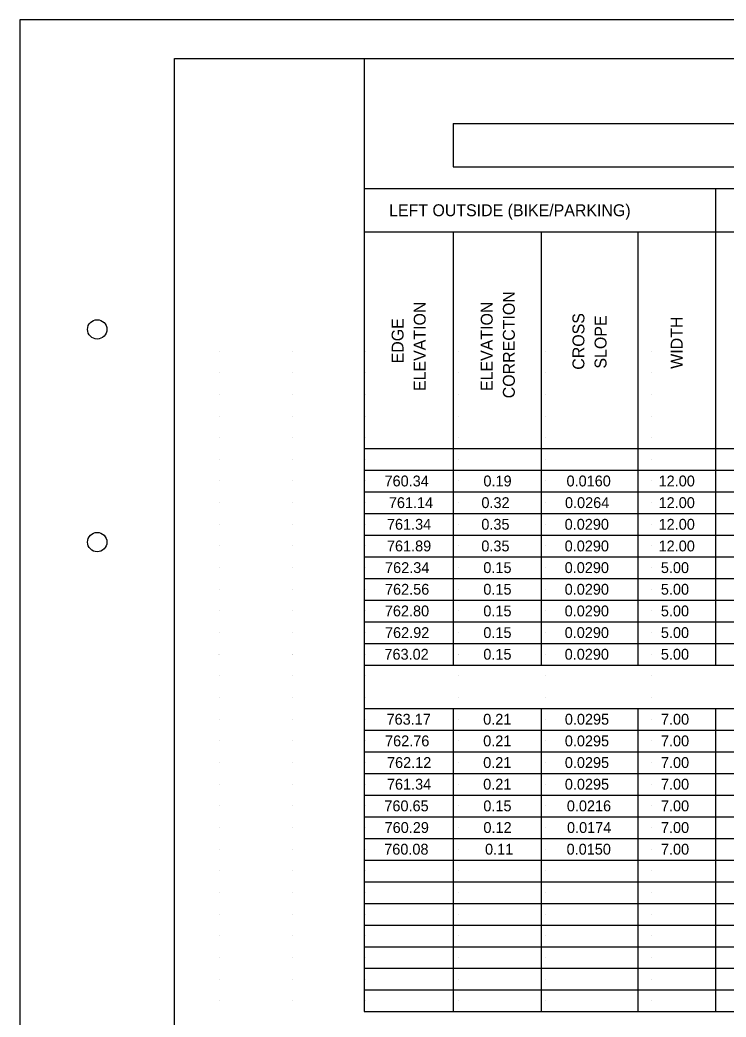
# Model space of a CAD drawing. Extents: x -15.4 to 18.6, y -12.6 to 9.4.
# Drawn here: x -15.36 to -6.22, y -3.5 to 9.39 of the extents above; entities that cross this region are included whole.
import ezdxf

# ---------------------------------------------------------------- set-up
doc = ezdxf.new("R2010")
doc.units = 0
for name, color, linetype in [('SH_Border', 7, 'Continuous'), ('SH_Cut_Line', 7, 'Continuous'), ('SH_Data', 7, 'Continuous'), ('SH_Text', 7, 'Continuous')]:
    doc.layers.add(name, color=color, linetype=linetype)

msp = doc.modelspace()

# ---------------------------------------------------------------- linework, layer by layer
at = {"layer": 'SH_Border'}
msp.add_lwpolyline([(-13.357, 8.888), (18.143, 8.888), (18.143, -12.112), (-13.357, -12.112)], close=True, dxfattribs=at)
for centre in [(-14.357, 5.388), (-14.357, 2.638)]:
    msp.add_circle(centre, 0.125, dxfattribs=at)
at = {"layer": 'SH_Cut_Line'}
msp.add_lwpolyline([(-15.357, -12.612), (18.643, -12.612), (18.643, 9.388), (-15.357, 9.388)], close=True, dxfattribs=at)
at = {"layer": 'SH_Data'}
for p, q in [((-10.905, 8.888), (13.093, 8.888)), ((-10.905, 8.888), (-10.905, -3.432)), ((-9.752, 8.048), (11.215, 8.048)), ((-9.752, 8.048), (-9.752, 7.488)), ((-9.752, 7.488), (11.215, 7.488)), ((-10.905, 7.208), (13.093, 7.208)), ((-6.359, 7.208), (-6.359, 1.048)), ((-10.905, 6.648), (11.791, 6.648)), ((-9.752, 6.648), (-9.752, 1.048)), ((-8.616, 6.648), (-8.616, 1.048)), ((-7.364, 6.648), (-7.364, 1.048)), ((-12.782, 5.108), (-12.782, 5.108)), ((-11.832, 5.108), (-11.832, 5.108)), ((-10.882, 5.108), (-10.882, 5.108)), ((-9.682, 5.108), (-9.682, 5.108)), ((-8.557, 5.108), (-8.557, 5.108)), ((-7.182, 5.108), (-7.182, 5.108)), ((-12.782, 4.828), (-12.782, 4.828)), ((-11.832, 4.828), (-11.832, 4.828)), ((-10.882, 4.828), (-10.882, 4.828)), ((-9.682, 4.828), (-9.682, 4.828)), ((-8.557, 4.828), (-8.557, 4.828)), ((-7.182, 4.828), (-7.182, 4.828)), ((-12.782, 4.548), (-12.782, 4.548)), ((-11.832, 4.548), (-11.832, 4.548)), ((-10.882, 4.548), (-10.882, 4.548)), ((-9.682, 4.548), (-9.682, 4.548)), ((-8.557, 4.548), (-8.557, 4.548)), ((-7.182, 4.548), (-7.182, 4.548)), ((-12.782, 4.268), (-12.782, 4.268)), ((-11.832, 4.268), (-11.832, 4.268)), ((-10.882, 4.268), (-10.882, 4.268)), ((-9.682, 4.268), (-9.682, 4.268)), ((-8.557, 4.268), (-8.557, 4.268)), ((-7.182, 4.268), (-7.182, 4.268)), ((-12.782, 3.988), (-12.782, 3.988)), ((-11.832, 3.988), (-11.832, 3.988)), ((-10.882, 3.988), (-10.882, 3.988)), ((-9.682, 3.988), (-9.682, 3.988)), ((-8.557, 3.988), (-8.557, 3.988)), ((-7.182, 3.988), (-7.182, 3.988)), ((-10.905, 3.848), (13.093, 3.848)), ((-12.782, 3.708), (-12.782, 3.708)), ((-11.832, 3.708), (-11.832, 3.708)), ((-10.882, 3.708), (-10.882, 3.708)), ((-9.682, 3.708), (-9.682, 3.708)), ((-8.557, 3.708), (-8.557, 3.708)), ((-7.182, 3.708), (-7.182, 3.708)), ((-10.905, 3.568), (13.093, 3.568)), ((-12.782, 3.428), (-12.782, 3.428)), ((-11.832, 3.428), (-11.832, 3.428)), ((-10.882, 3.428), (-10.882, 3.428)), ((-9.682, 3.428), (-9.682, 3.428)), ((-8.557, 3.428), (-8.557, 3.428)), ((-7.182, 3.428), (-7.182, 3.428)), ((-10.905, 3.288), (13.093, 3.288)), ((-12.782, 3.148), (-12.782, 3.148)), ((-11.832, 3.148), (-11.832, 3.148)), ((-10.882, 3.148), (-10.882, 3.148)), ((-9.682, 3.148), (-9.682, 3.148)), ((-8.557, 3.148), (-8.557, 3.148)), ((-7.182, 3.148), (-7.182, 3.148)), ((-10.905, 3.008), (13.093, 3.008)), ((-12.782, 2.868), (-12.782, 2.868)), ((-11.832, 2.868), (-11.832, 2.868)), ((-10.882, 2.868), (-10.882, 2.868)), ((-9.682, 2.868), (-9.682, 2.868)), ((-8.557, 2.868), (-8.557, 2.868)), ((-7.182, 2.868), (-7.182, 2.868)), ((-10.905, 2.728), (13.093, 2.728)), ((-12.782, 2.588), (-12.782, 2.588)), ((-11.832, 2.588), (-11.832, 2.588)), ((-10.882, 2.588), (-10.882, 2.588)), ((-9.682, 2.588), (-9.682, 2.588)), ((-8.557, 2.588), (-8.557, 2.588)), ((-7.182, 2.588), (-7.182, 2.588)), ((-10.905, 2.448), (13.093, 2.448)), ((-12.782, 2.308), (-12.782, 2.308)), ((-11.832, 2.308), (-11.832, 2.308)), ((-10.882, 2.308), (-10.882, 2.308)), ((-9.682, 2.308), (-9.682, 2.308)), ((-8.557, 2.308), (-8.557, 2.308)), ((-7.182, 2.308), (-7.182, 2.308)), ((-10.905, 2.168), (13.093, 2.168)), ((-12.782, 2.028), (-12.782, 2.028)), ((-11.832, 2.028), (-11.832, 2.028)), ((-10.882, 2.028), (-10.882, 2.028)), ((-9.682, 2.028), (-9.682, 2.028)), ((-8.557, 2.028), (-8.557, 2.028)), ((-7.182, 2.028), (-7.182, 2.028)), ((-10.905, 1.888), (13.093, 1.888)), ((-12.782, 1.748), (-12.782, 1.748)), ((-12.782, 1.748), (-12.782, 1.748)), ((-11.832, 1.748), (-11.832, 1.748)), ((-11.832, 1.748), (-11.832, 1.748)), ((-10.882, 1.748), (-10.882, 1.748)), ((-10.882, 1.748), (-10.882, 1.748)), ((-9.682, 1.748), (-9.682, 1.748)), ((-9.682, 1.748), (-9.682, 1.748)), ((-8.557, 1.748), (-8.557, 1.748)), ((-8.557, 1.748), (-8.557, 1.748)), ((-7.182, 1.748), (-7.182, 1.748)), ((-7.182, 1.748), (-7.182, 1.748)), ((-10.905, 1.608), (13.093, 1.608)), ((-12.782, 1.468), (-12.782, 1.468)), ((-12.782, 1.468), (-12.782, 1.468)), ((-11.832, 1.468), (-11.832, 1.468)), ((-11.832, 1.468), (-11.832, 1.468)), ((-10.882, 1.468), (-10.882, 1.468)), ((-10.882, 1.468), (-10.882, 1.468)), ((-9.682, 1.468), (-9.682, 1.468)), ((-9.682, 1.468), (-9.682, 1.468)), ((-8.557, 1.468), (-8.557, 1.468)), ((-8.557, 1.468), (-8.557, 1.468)), ((-7.182, 1.468), (-7.182, 1.468)), ((-7.182, 1.468), (-7.182, 1.468)), ((-10.905, 1.328), (13.093, 1.328)), ((-12.785, 1.188), (-12.785, 1.188)), ((-12.785, 1.188), (-12.785, 1.188)), ((-12.782, 1.188), (-12.782, 1.188)), ((-11.835, 1.188), (-11.835, 1.188)), ((-11.835, 1.188), (-11.835, 1.188)), ((-11.832, 1.188), (-11.832, 1.188)), ((-10.885, 1.188), (-10.885, 1.188)), ((-10.885, 1.188), (-10.885, 1.188)), ((-10.882, 1.188), (-10.882, 1.188)), ((-9.685, 1.188), (-9.685, 1.188)), ((-9.685, 1.188), (-9.685, 1.188)), ((-9.682, 1.188), (-9.682, 1.188)), ((-8.56, 1.188), (-8.56, 1.188)), ((-8.56, 1.188), (-8.56, 1.188)), ((-8.557, 1.188), (-8.557, 1.188)), ((-7.185, 1.188), (-7.185, 1.188)), ((-7.185, 1.188), (-7.185, 1.188)), ((-7.182, 1.188), (-7.182, 1.188)), ((-10.905, 1.048), (13.093, 1.048)), ((-12.782, 0.908), (-12.782, 0.908)), ((-11.832, 0.908), (-11.832, 0.908)), ((-10.882, 0.908), (-10.882, 0.908)), ((-9.682, 0.908), (-9.682, 0.908)), ((-8.557, 0.908), (-8.557, 0.908)), ((-7.182, 0.908), (-7.182, 0.908)), ((-12.782, 0.628), (-12.782, 0.628)), ((-11.832, 0.628), (-11.832, 0.628)), ((-10.882, 0.628), (-10.882, 0.628)), ((-9.682, 0.628), (-9.682, 0.628)), ((-8.557, 0.628), (-8.557, 0.628)), ((-7.182, 0.628), (-7.182, 0.628)), ((-10.905, 0.488), (13.093, 0.488)), ((-9.752, 0.488), (-9.752, -3.432)), ((-8.616, 0.488), (-8.616, -3.432)), ((-7.364, 0.488), (-7.364, -3.432)), ((-6.359, 0.488), (-6.359, -3.432)), ((-12.782, 0.348), (-12.782, 0.348)), ((-11.832, 0.348), (-11.832, 0.348)), ((-10.882, 0.348), (-10.882, 0.348)), ((-9.682, 0.348), (-9.682, 0.348)), ((-8.557, 0.348), (-8.557, 0.348)), ((-7.182, 0.348), (-7.182, 0.348)), ((-10.905, 0.208), (13.093, 0.208)), ((-12.782, 0.068), (-12.782, 0.068)), ((-11.832, 0.068), (-11.832, 0.068)), ((-10.882, 0.068), (-10.882, 0.068)), ((-9.682, 0.068), (-9.682, 0.068)), ((-8.557, 0.068), (-8.557, 0.068)), ((-7.182, 0.068), (-7.182, 0.068)), ((-10.905, -0.072), (13.093, -0.072)), ((-12.782, -0.212), (-12.782, -0.212)), ((-11.832, -0.212), (-11.832, -0.212)), ((-10.882, -0.212), (-10.882, -0.212)), ((-9.682, -0.212), (-9.682, -0.212)), ((-8.557, -0.212), (-8.557, -0.212)), ((-7.182, -0.212), (-7.182, -0.212)), ((-10.905, -0.352), (13.093, -0.352)), ((-12.782, -0.492), (-12.782, -0.492)), ((-11.832, -0.492), (-11.832, -0.492)), ((-10.882, -0.492), (-10.882, -0.492)), ((-9.682, -0.492), (-9.682, -0.492)), ((-8.557, -0.492), (-8.557, -0.492)), ((-7.182, -0.492), (-7.182, -0.492)), ((-10.905, -0.632), (13.093, -0.632)), ((-12.782, -0.772), (-12.782, -0.772)), ((-11.832, -0.772), (-11.832, -0.772)), ((-10.882, -0.772), (-10.882, -0.772)), ((-9.682, -0.772), (-9.682, -0.772)), ((-8.557, -0.772), (-8.557, -0.772)), ((-7.182, -0.772), (-7.182, -0.772)), ((-10.905, -0.912), (13.093, -0.912)), ((-12.782, -1.052), (-12.782, -1.052)), ((-11.832, -1.052), (-11.832, -1.052)), ((-10.882, -1.052), (-10.882, -1.052)), ((-9.682, -1.052), (-9.682, -1.052)), ((-8.557, -1.052), (-8.557, -1.052)), ((-7.182, -1.052), (-7.182, -1.052)), ((-10.905, -1.192), (13.093, -1.192)), ((-12.782, -1.332), (-12.782, -1.332)), ((-11.832, -1.332), (-11.832, -1.332)), ((-10.882, -1.332), (-10.882, -1.332)), ((-9.682, -1.332), (-9.682, -1.332)), ((-8.557, -1.332), (-8.557, -1.332)), ((-7.182, -1.332), (-7.182, -1.332)), ((-10.905, -1.472), (13.093, -1.472)), ((-12.782, -1.612), (-12.782, -1.612)), ((-11.832, -1.612), (-11.832, -1.612)), ((-10.882, -1.612), (-10.882, -1.612)), ((-9.682, -1.612), (-9.682, -1.612)), ((-8.557, -1.612), (-8.557, -1.612)), ((-7.182, -1.612), (-7.182, -1.612)), ((-10.905, -1.752), (13.093, -1.752)), ((-12.782, -1.892), (-12.782, -1.892)), ((-11.832, -1.892), (-11.832, -1.892)), ((-10.882, -1.892), (-10.882, -1.892)), ((-9.682, -1.892), (-9.682, -1.892)), ((-8.557, -1.892), (-8.557, -1.892)), ((-7.182, -1.892), (-7.182, -1.892)), ((-10.905, -2.032), (13.093, -2.032)), ((-12.782, -2.172), (-12.782, -2.172)), ((-11.832, -2.172), (-11.832, -2.172)), ((-10.882, -2.172), (-10.882, -2.172)), ((-9.682, -2.172), (-9.682, -2.172)), ((-8.557, -2.172), (-8.557, -2.172)), ((-7.182, -2.172), (-7.182, -2.172)), ((-10.905, -2.312), (13.093, -2.312)), ((-12.782, -2.452), (-12.782, -2.452)), ((-11.832, -2.452), (-11.832, -2.452)), ((-10.882, -2.452), (-10.882, -2.452)), ((-9.682, -2.452), (-9.682, -2.452)), ((-8.557, -2.452), (-8.557, -2.452)), ((-7.182, -2.452), (-7.182, -2.452)), ((-10.905, -2.592), (13.093, -2.592)), ((-12.782, -2.732), (-12.782, -2.732)), ((-11.832, -2.732), (-11.832, -2.732)), ((-10.882, -2.732), (-10.882, -2.732)), ((-9.682, -2.732), (-9.682, -2.732)), ((-8.557, -2.732), (-8.557, -2.732)), ((-7.182, -2.732), (-7.182, -2.732)), ((-10.905, -2.872), (13.093, -2.872)), ((-12.782, -3.012), (-12.782, -3.012)), ((-11.832, -3.012), (-11.832, -3.012)), ((-10.882, -3.012), (-10.882, -3.012)), ((-9.682, -3.012), (-9.682, -3.012)), ((-8.557, -3.012), (-8.557, -3.012)), ((-7.182, -3.012), (-7.182, -3.012)), ((-10.905, -3.152), (13.093, -3.152)), ((-12.782, -3.292), (-12.782, -3.292)), ((-11.832, -3.292), (-11.832, -3.292)), ((-10.882, -3.292), (-10.882, -3.292)), ((-9.682, -3.292), (-9.682, -3.292)), ((-8.557, -3.292), (-8.557, -3.292)), ((-7.182, -3.292), (-7.182, -3.292)), ((-10.905, -3.432), (13.093, -3.432))]:
    msp.add_line(p, q, dxfattribs=at)

# ---------------------------------------------------------------- texts
at = {"layer": 'SH_Text'}
for s, height, p in [('LEFT OUTSIDE (BIKE/PARKING)', 0.154, (-10.582, 6.851)), ('760.34', 0.14, (-10.641, 3.358)), ('0.19', 0.14, (-9.362, 3.358)), ('0.0160', 0.14, (-8.287, 3.358)), ('12.00', 0.14, (-7.096, 3.358)), ('761.14', 0.14, (-10.585, 3.078)), ('0.32', 0.14, (-9.388, 3.078)), ('0.0264', 0.14, (-8.307, 3.078)), ('12.00', 0.14, (-7.096, 3.078)), ('761.34', 0.14, (-10.61, 2.798)), ('0.35', 0.14, (-9.389, 2.798)), ('0.0290', 0.14, (-8.311, 2.798)), ('12.00', 0.14, (-7.096, 2.798)), ('761.89', 0.14, (-10.61, 2.518)), ('0.35', 0.14, (-9.389, 2.518)), ('0.0290', 0.14, (-8.311, 2.518)), ('12.00', 0.14, (-7.096, 2.518)), ('762.34', 0.14, (-10.634, 2.238)), ('0.15', 0.14, (-9.363, 2.238)), ('0.0290', 0.14, (-8.311, 2.238)), ('5.00', 0.14, (-7.067, 2.238)), ('762.56', 0.14, (-10.635, 1.958)), ('0.15', 0.14, (-9.363, 1.958)), ('0.0290', 0.14, (-8.311, 1.958)), ('5.00', 0.14, (-7.067, 1.958)), ('762.80', 0.14, (-10.637, 1.678)), ('0.15', 0.14, (-9.363, 1.678)), ('0.0290', 0.14, (-8.311, 1.678)), ('5.00', 0.14, (-7.067, 1.678)), ('762.92', 0.14, (-10.635, 1.398)), ('0.15', 0.14, (-9.363, 1.398)), ('0.0290', 0.14, (-8.311, 1.398)), ('5.00', 0.14, (-7.067, 1.398)), ('763.02', 0.14, (-10.642, 1.118)), ('0.15', 0.14, (-9.363, 1.118)), ('0.0290', 0.14, (-8.311, 1.118)), ('5.00', 0.14, (-7.067, 1.118)), ('763.17', 0.14, (-10.615, 0.278)), ('0.21', 0.14, (-9.365, 0.278)), ('0.0295', 0.14, (-8.309, 0.278)), ('7.00', 0.14, (-7.066, 0.278)), ('762.76', 0.14, (-10.634, -0.002)), ('0.21', 0.14, (-9.365, -0.002)), ('0.0295', 0.14, (-8.309, -0.002)), ('7.00', 0.14, (-7.066, -0.002)), ('762.12', 0.14, (-10.609, -0.282)), ('0.21', 0.14, (-9.365, -0.282)), ('0.0295', 0.14, (-8.309, -0.282)), ('7.00', 0.14, (-7.066, -0.282)), ('761.34', 0.14, (-10.61, -0.562)), ('0.21', 0.14, (-9.365, -0.562)), ('0.0295', 0.14, (-8.309, -0.562)), ('7.00', 0.14, (-7.066, -0.562)), ('760.65', 0.14, (-10.643, -0.842)), ('0.15', 0.14, (-9.363, -0.842)), ('0.0216', 0.14, (-8.283, -0.842)), ('7.00', 0.14, (-7.066, -0.842)), ('760.29', 0.14, (-10.64, -1.122)), ('0.12', 0.14, (-9.362, -1.122)), ('0.0174', 0.14, (-8.281, -1.122)), ('7.00', 0.14, (-7.066, -1.122)), ('760.08', 0.14, (-10.645, -1.402)), ('0.11', 0.14, (-9.341, -1.402)), ('0.0150', 0.14, (-8.286, -1.402)), ('7.00', 0.14, (-7.066, -1.402))]:
    msp.add_text(s, height=height, dxfattribs=at).set_placement(p)
for s, p in [('CORRECTION', (-8.956, 4.497)), ('ELEVATION', (-10.109, 4.591)), ('ELEVATION', (-9.242, 4.591)), ('CROSS', (-8.056, 4.866)), ('SLOPE', (-7.77, 4.881)), ('EDGE', (-10.395, 4.948)), ('WIDTH', (-6.785, 4.878))]:
    msp.add_text(s, height=0.154, rotation=90, dxfattribs=at).set_placement(p)

doc.saveas('drawing.dxf')
